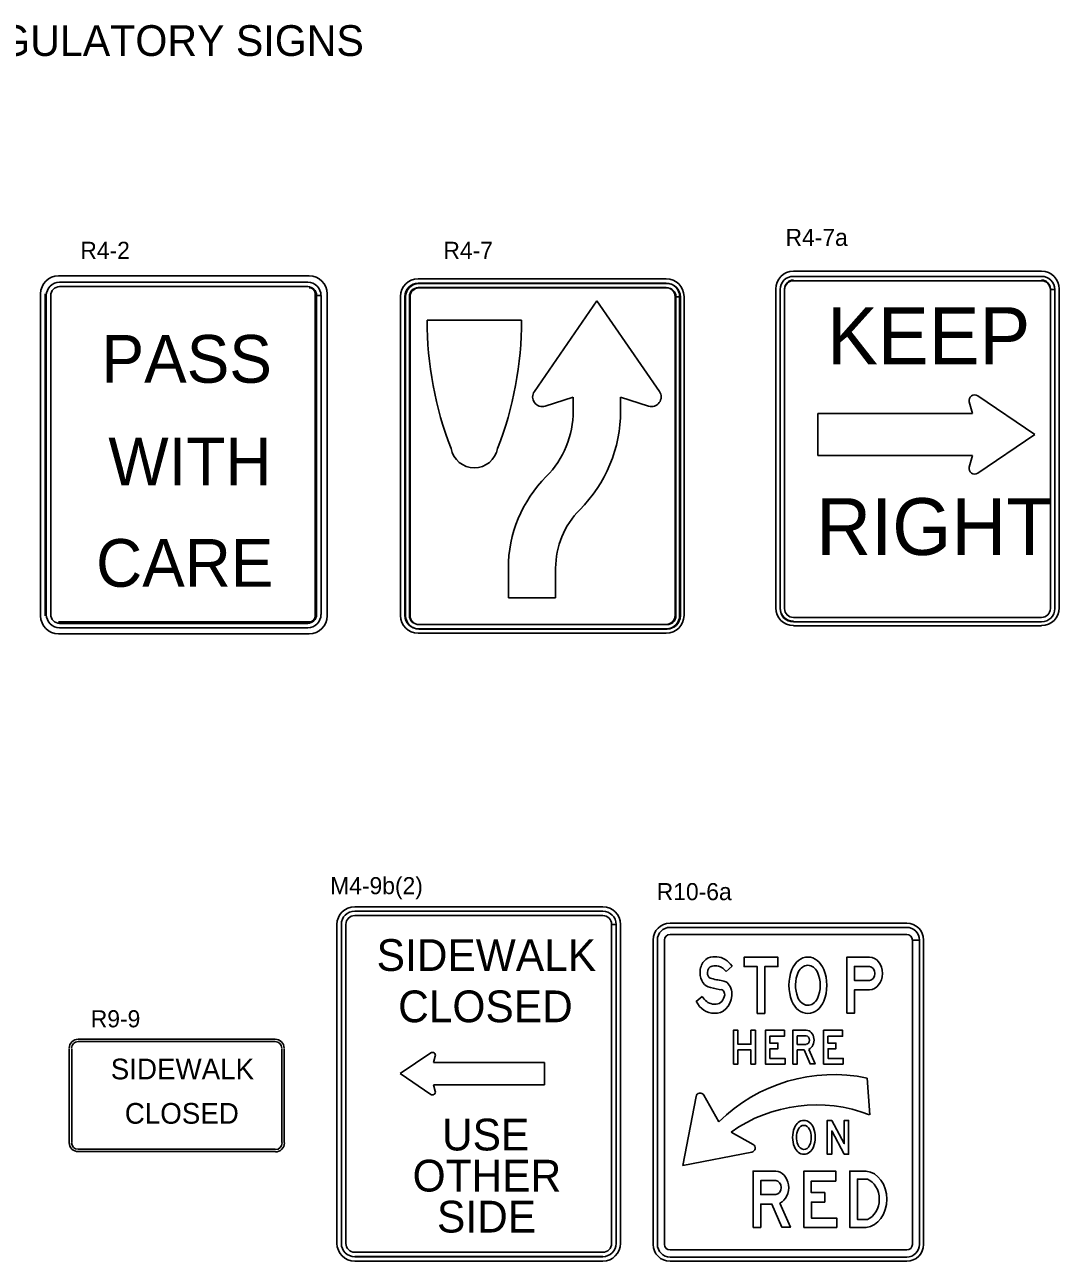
# Model space of a CAD drawing. Extents: x 1531.6 to 1538.58, y 1529.59 to 1539.33.
# Drawn here: x 1534.427 to 1538.059, y 1534.989 to 1539.332 of the extents above; entities that cross this region are included whole.
import ezdxf

# ---------------------------------------------------------------- set-up
doc = ezdxf.new("R2010")
doc.units = 0
for name, color, linetype in [('DETL-LINE', 7, 'Continuous'), ('DETL-NOTE', 7, 'Continuous'), ('DETL-TITL', 7, 'Continuous'), ('USER-BORD', 7, 'Continuous')]:
    doc.layers.add(name, color=color, linetype=linetype)

# ---------------------------------------------------------------- blocks, each defined once
blk = doc.blocks.new('EBK830')
at = {"layer": 'USER-BORD'}
for p, q in [((19.2, 20.1), (16.06, 17.76)), ((0, 5.1), (3.29, 7.2))]:
    blk.add_line(p, q, dxfattribs=at)
for centre, radius, start, end in [((8.82, 17.32), 6.73, 88.8922, 179.7586), ((10, 13.17), 10.93, 84.3792, 95.4986), ((10.65, 12.82), 11.23, 40.4161, 87.8422), ((8.44, 17.26), 6.35, 179.1866, 262.9776), ((8.82, 17.32), 2.83, 94.4353, 180.1618), ((8.44, 17.26), 2.45, 178.7407, 247.3216), ((10.01, 11.65), 8.61, 77.3888, 99.3796), ((10.65, 12.82), 7.33, 42.3579, 80.2675), ((18.43, 59.96), 46.27, 256.3309, 264.6653), ((18.43, 59.96), 50.17, 257.6081, 264.6653), ((11.77, 2.75), 11.39, 65.6571, 78.0474), ((12.65, 7.91), 6.47, 356.2163, 53.7856), ((9.6, 11.59), 7.68, 214.8089, 262.9285), ((10.37, 8.8), 8.83, 264.982, 351.4116), ((10.37, 8.8), 4.93, 273.4628, 349.3461), ((11.77, 2.75), 7.49, 69.1712, 78.0474), ((12.65, 7.91), 2.57, 359.563, 45.8128), ((9.6, 11.59), 11.58, 214.036, 269.995), ((10.06, 13.59), 9.73, 261.6866, 273.58), ((12.65, 7.91), 6.47, 317.7059, 321.0526)]:
    blk.add_arc(centre, radius, start, end, dxfattribs=at)
blk = doc.blocks.new('EBK840')
at = {"layer": 'USER-BORD'}
blk.add_lwpolyline([(11.0241, -0.0679), (7.028, -0.0679), (7.028, 19.9126), (0.026, 19.9126), (0.026, 23.9087), (18.026, 23.9087), (18.026, 19.9126), (11.0241, 19.9126)], close=True, dxfattribs=at)
blk = doc.blocks.new('EBK790')
at = {"layer": 'USER-BORD'}
for centre, radius, start, end in [((10, 14.51), 9.43, 26.0505, 153.9495), ((14.77, 11.93), 14.84, 153.1125, 206.8875), ((14.77, 11.93), 11.34, 150.334, 206.8875), ((10, 14.51), 5.93, 30.8734, 149.1266), ((5.23, 11.93), 11.34, 330.334, 29.666), ((5.23, 11.93), 14.84, 333.1125, 26.8875), ((10, 9.36), 5.93, 206.0505, 329.1266), ((10, 9.36), 9.43, 206.0505, 333.9495)]:
    blk.add_arc(centre, radius, start, end, dxfattribs=at)
blk = doc.blocks.new('EBK800')
at = {"layer": 'USER-BORD'}
for points in [[(0, 0), (0, 23.98), (4, 23.98), (12, 23.98)], [(12, 19.98), (4, 19.98), (4, 13.98), (12, 13.98)], [(12, 9.98), (4, 9.98), (4, 0), (0, 0)]]:
    blk.add_lwpolyline(points, dxfattribs=at)
for radius, start, end in [(7, 270.7924, 89.2076), (3, 271.865, 88.135)]:
    blk.add_arc((11.9, 16.98), radius, start, end, dxfattribs=at)
blk = doc.blocks.new('EBK720')
at = {"layer": 'USER-BORD'}
blk.add_lwpolyline([(0, 0), (0, 24), (4, 24), (4, 14), (15.5, 14), (15.5, 24), (19.5, 24), (19.5, 0), (15.5, 0), (15.5, 10), (4, 10), (4, 0)], close=True, dxfattribs=at)
blk = doc.blocks.new('EBK690')
at = {"layer": 'USER-BORD'}
blk.add_lwpolyline([(17.4295, 0), (17.4295, 4), (3.9496, 4), (3.9496, 10.8235), (11.0254, 10.8235), (11.0254, 14.8235), (3.8378, 14.8235), (3.8378, 19.7541), (16.9123, 19.7541), (16.9123, 24.0149), (0, 24.0149), (0, 0)], close=True, dxfattribs=at)
blk = doc.blocks.new('EBK820')
at = {"layer": 'USER-BORD'}
for points in [[(0, 0), (0, 23.98), (4, 23.98), (12, 23.98)], [(12, 19.98), (4, 19.98), (4, 13.98), (12, 13.98)], [(14.28, 10.4), (19.8, 0.05), (15.3, 0.05), (10, 9.98), (4, 9.98), (4, 0), (0, 0)]]:
    blk.add_lwpolyline(points, dxfattribs=at)
for radius, start, end in [(7, 289.8173, 89.2076), (3, 271.865, 88.135)]:
    blk.add_arc((11.9, 16.98), radius, start, end, dxfattribs=at)
blk = doc.blocks.new('EBK780')
at = {"layer": 'USER-BORD'}
blk.add_lwpolyline([(15, 0), (3.9, 16.5), (3.9, 0), (0, 0), (0, 24), (3.9, 24), (15, 7.5), (15, 24), (18.9, 24), (18.9, 0)], close=True, dxfattribs=at)
blk = doc.blocks.new('EBK680')
at = {"layer": 'USER-BORD'}
for p, q in [((8.75, 24), (8.75, 24)), ((9.36, 20.61), (9.36, 20.61))]:
    blk.add_line(p, q, dxfattribs=at)
for points in [[(8.75, 0), (0, 0), (0, 24), (8.75, 24)], [(9.36, 20.61), (4.05, 20.61), (4.05, 3.4), (9.36, 3.4)]]:
    blk.add_lwpolyline(points, dxfattribs=at)
for centre, radius, start, end in [((7.65, 12), 12.05, 275.2185, 84.7815), ((6.65, 12), 9.02, 287.4703, 72.5297)]:
    blk.add_arc(centre, radius, start, end, dxfattribs=at)

msp = doc.modelspace()

# ---------------------------------------------------------------- linework, layer by layer
at = {"layer": 'DETL-LINE'}
for p, q in [((1535.4256, 1538.4501), (1534.5453, 1538.4501)), ((1537.9972, 1538.4659), (1537.1259, 1538.4659)), ((1534.549, 1538.4275), (1535.4202, 1538.4275)), ((1535.4202, 1538.4119), (1534.549, 1538.4119)), ((1536.6795, 1538.4395), (1535.8083, 1538.4395)), ((1536.6795, 1538.424), (1535.8083, 1538.424)), ((1536.6795, 1538.4084), (1535.8083, 1538.4084)), ((1535.8108, 1538.4231), (1536.6821, 1538.4231)), ((1536.6821, 1538.4075), (1535.8108, 1538.4075)), ((1537.1258, 1538.4481), (1537.997, 1538.4481)), ((1537.997, 1538.4325), (1537.1258, 1538.4325)), ((1534.4824, 1538.3873), (1534.4824, 1537.2555)), ((1534.498, 1538.3873), (1534.498, 1537.2555)), ((1534.5024, 1537.2606), (1534.5024, 1538.3808)), ((1534.5179, 1538.3808), (1534.5179, 1537.2606)), ((1535.4465, 1537.2555), (1535.4465, 1538.3873)), ((1535.4514, 1537.2606), (1535.4514, 1538.3808)), ((1535.4514, 1538.3808), (1535.467, 1538.3808)), ((1535.467, 1538.3808), (1535.467, 1537.2606)), ((1535.4884, 1537.2555), (1535.4884, 1538.3873)), ((1535.7461, 1538.3773), (1535.7461, 1537.2571)), ((1535.7616, 1538.3773), (1535.7616, 1537.2571)), ((1535.7642, 1537.2562), (1535.7642, 1538.3764)), ((1535.7772, 1538.3773), (1535.7772, 1537.2571)), ((1535.7798, 1538.3764), (1535.7798, 1537.2562)), ((1536.4358, 1538.3617), (1536.2162, 1538.0438)), ((1536.4358, 1538.3617), (1536.6554, 1538.0438)), ((1536.6554, 1538.0438), (1536.4358, 1538.3617)), ((1536.6554, 1538.0438), (1536.4358, 1538.3617)), ((1536.7106, 1537.2571), (1536.7106, 1538.3773)), ((1536.7132, 1537.2562), (1536.7132, 1538.3764)), ((1536.7132, 1538.3764), (1536.7288, 1538.3764)), ((1536.7262, 1537.2571), (1536.7262, 1538.3773)), ((1536.7288, 1538.3764), (1536.7288, 1537.2562)), ((1536.7418, 1537.2571), (1536.7418, 1538.3773)), ((1537.0637, 1538.4038), (1537.0637, 1537.2836)), ((1537.0792, 1537.2812), (1537.0792, 1538.4014)), ((1537.0793, 1538.4038), (1537.0793, 1537.2836)), ((1537.0947, 1538.4014), (1537.0947, 1537.2812)), ((1537.0948, 1538.4038), (1537.0948, 1537.2836)), ((1538.0282, 1537.2812), (1538.0282, 1538.4014)), ((1538.0282, 1538.4014), (1538.0438, 1538.4014)), ((1538.0283, 1537.2836), (1538.0283, 1538.4038)), ((1538.0438, 1538.4014), (1538.0438, 1537.2812)), ((1538.0439, 1537.2836), (1538.0439, 1538.4038)), ((1538.0594, 1537.2836), (1538.0594, 1538.4038)), ((1535.8394, 1538.2943), (1536.1713, 1538.2943)), ((1536.1713, 1538.2943), (1536.1713, 1538.2943)), ((1536.2542, 1537.9925), (1536.3529, 1538.0241)), ((1536.3529, 1538.0241), (1536.3529, 1537.9753)), ((1536.5188, 1537.9753), (1536.5188, 1538.0241)), ((1536.5188, 1538.0241), (1536.6174, 1537.9925)), ((1536.6554, 1538.0438), (1536.6554, 1538.0438)), ((1537.7728, 1538.0285), (1537.7729, 1538.0285)), ((1537.7729, 1538.0285), (1537.9734, 1537.8926)), ((1537.7549, 1537.9667), (1537.7434, 1538.0071)), ((1537.2119, 1537.8187), (1537.2119, 1537.9667)), ((1537.2119, 1537.9667), (1537.7549, 1537.9667)), ((1537.9734, 1537.8926), (1537.7729, 1537.7569)), ((1537.7549, 1537.8187), (1537.2119, 1537.8187)), ((1537.7434, 1537.7782), (1537.7549, 1537.8187)), ((1536.1248, 1537.4231), (1536.1248, 1537.3194)), ((1536.2907, 1537.3194), (1536.2907, 1537.4231)), ((1536.1248, 1537.3194), (1536.2907, 1537.3194)), ((1534.5453, 1537.2345), (1535.4256, 1537.2345)), ((1537.1258, 1537.2501), (1537.997, 1537.2501)), ((1537.997, 1537.2346), (1537.1258, 1537.2346)), ((1534.5453, 1537.1926), (1535.4256, 1537.1926)), ((1534.549, 1537.2295), (1535.4202, 1537.2295)), ((1535.4202, 1537.214), (1534.549, 1537.214)), ((1535.8083, 1537.2259), (1536.6795, 1537.2259)), ((1535.8083, 1537.2104), (1536.6795, 1537.2104)), ((1535.8083, 1537.1949), (1536.6795, 1537.1949)), ((1535.8108, 1537.2251), (1536.6821, 1537.2251)), ((1536.6821, 1537.2096), (1535.8108, 1537.2096)), ((1537.1259, 1537.2213), (1537.9972, 1537.2213)), ((1535.5852, 1536.2343), (1536.4565, 1536.2343)), ((1535.5852, 1536.2188), (1536.4565, 1536.2188)), ((1535.5852, 1536.2187), (1536.4565, 1536.2187)), ((1535.5852, 1536.2032), (1536.4565, 1536.2032)), ((1536.4565, 1536.2032), (1535.5852, 1536.2032)), ((1535.523, 1535.0519), (1535.523, 1536.1721)), ((1535.5386, 1535.0519), (1535.5386, 1536.1721)), ((1535.5386, 1535.0519), (1535.5386, 1536.1721)), ((1535.554, 1535.0519), (1535.554, 1536.1721)), ((1535.5541, 1536.1721), (1535.5541, 1535.0519)), ((1536.4876, 1536.1721), (1536.4876, 1535.0519)), ((1536.4876, 1535.0519), (1536.4876, 1536.1721)), ((1536.4876, 1536.1721), (1536.5032, 1536.1721)), ((1536.5032, 1536.1721), (1536.5032, 1535.0519)), ((1536.5032, 1536.1721), (1536.5032, 1535.0519)), ((1536.5187, 1536.1721), (1536.5187, 1535.0519)), ((1537.5238, 1536.1765), (1536.6926, 1536.1765)), ((1537.5238, 1536.1617), (1536.6926, 1536.1617)), ((1536.6332, 1536.1172), (1536.6332, 1535.0485)), ((1536.6481, 1536.1172), (1536.6481, 1535.0485)), ((1536.6728, 1535.0485), (1536.6728, 1536.1172)), ((1536.6926, 1536.1369), (1537.5238, 1536.1369)), ((1537.5683, 1536.1172), (1537.5436, 1536.1172)), ((1537.5436, 1536.1172), (1537.5436, 1535.0485)), ((1537.5683, 1535.0485), (1537.5683, 1536.1172)), ((1537.5832, 1535.0485), (1537.5832, 1536.1172)), ((1535.306, 1535.769), (1534.6144, 1535.769)), ((1535.306, 1535.7606), (1534.6144, 1535.7606)), ((1534.583, 1535.7351), (1534.583, 1535.4066)), ((1534.5914, 1535.7351), (1534.5914, 1535.4066)), ((1535.3291, 1535.4066), (1535.3291, 1535.7351)), ((1535.3374, 1535.4066), (1535.3374, 1535.7351)), ((1535.8526, 1535.7209), (1535.745, 1535.6481)), ((1535.8622, 1535.6877), (1535.8684, 1535.7096)), ((1536.252, 1535.6877), (1535.8622, 1535.6877)), ((1536.252, 1535.6084), (1536.252, 1535.6877)), ((1535.745, 1535.6481), (1535.8526, 1535.5752)), ((1537.3937, 1535.5037), (1537.3848, 1535.6323)), ((1537.3848, 1535.6323), (1537.3848, 1535.6323)), ((1535.8684, 1535.5867), (1535.8622, 1535.6084)), ((1535.8622, 1535.6084), (1536.252, 1535.6084)), ((1536.7838, 1535.568), (1536.7371, 1535.3256)), ((1536.864, 1535.4789), (1536.8113, 1535.5725)), ((1536.9841, 1535.3997), (1536.9073, 1535.4429)), ((1534.6144, 1535.3825), (1535.306, 1535.3825)), ((1534.6144, 1535.3741), (1535.306, 1535.3741)), ((1536.7371, 1535.3256), (1536.9796, 1535.3722)), ((1535.5852, 1535.0208), (1536.4565, 1535.0208)), ((1536.4565, 1535.0207), (1535.5852, 1535.0207)), ((1537.5238, 1535.0287), (1536.6926, 1535.0287)), ((1537.5683, 1535.0485), (1537.5683, 1535.0485)), ((1536.4565, 1535.0053), (1535.5852, 1535.0053)), ((1536.4565, 1535.0052), (1535.5852, 1535.0052)), ((1536.4565, 1534.9897), (1535.5852, 1534.9897)), ((1536.6926, 1535.0039), (1537.5238, 1535.0039)), ((1536.6926, 1534.9891), (1537.5238, 1534.9891))]:
    msp.add_line(p, q, dxfattribs=at)
for centre, radius, start, end in [((1534.5452, 1538.3872), 0.0629, 90, 180), ((1535.4255, 1538.3872), 0.0629, 0, 90), ((1537.1259, 1538.4038), 0.0622, 90, 180), ((1537.9972, 1538.4038), 0.0622, 0, 90), ((1534.549, 1538.3808), 0.0467, 90, 180), ((1534.549, 1538.3808), 0.0311, 90, 180), ((1535.4202, 1538.3808), 0.0467, 0, 90), ((1535.4202, 1538.3808), 0.0311, 0, 90), ((1535.4255, 1538.3872), 0.021, 0, 90), ((1535.8083, 1538.3773), 0.0622, 90, 180), ((1535.8083, 1538.3773), 0.0467, 90, 180), ((1535.8109, 1538.3764), 0.0467, 90, 180), ((1535.8083, 1538.3773), 0.0311, 90, 180), ((1535.8109, 1538.3764), 0.0311, 90, 180), ((1536.6795, 1538.3773), 0.0622, 0, 90), ((1536.6795, 1538.3773), 0.0467, 0, 90), ((1536.6795, 1538.3773), 0.0311, 0, 90), ((1536.6821, 1538.3764), 0.0467, 0, 90), ((1536.6821, 1538.3764), 0.0311, 0, 90), ((1537.1258, 1538.4014), 0.0467, 90, 180), ((1537.1258, 1538.4014), 0.0311, 90, 180), ((1537.1259, 1538.4038), 0.0311, 90, 180), ((1537.997, 1538.4014), 0.0467, 0, 90), ((1537.997, 1538.4014), 0.0311, 0, 90), ((1537.9972, 1538.4038), 0.0311, 0, 90), ((1537.084, 1538.2939), 1.2447, 179.9823, 201.2203), ((1534.9266, 1538.2939), 1.2447, 338.7797, 0.0177), ((1536.2439, 1538.0246), 0.0337, 145.3645, 287.7219), ((1536.6277, 1538.0246), 0.0337, 252.2781, 34.6356), ((1537.762, 1538.0124), 0.0194, 55.8869, 195.9549), ((1536.0263, 1537.9754), 0.3266, 315.1342, 0), ((1536.0263, 1537.9754), 0.4925, 315.1342, 0), ((1536.0053, 1537.8587), 0.083, 190.6013, 349.3987), ((1537.762, 1537.7729), 0.0194, 164.0451, 304.1131), ((1536.5812, 1537.423), 0.4564, 135.1342, 180), ((1536.5812, 1537.423), 0.2904, 135.1342, 180), ((1537.1259, 1537.2836), 0.0622, 180, 270), ((1537.1259, 1537.2836), 0.0467, 180, 270), ((1537.1258, 1537.2812), 0.0467, 180, 270), ((1537.1258, 1537.2812), 0.0311, 180, 270), ((1537.997, 1537.2812), 0.0467, 270, 0), ((1537.997, 1537.2812), 0.0311, 270, 0), ((1537.9972, 1537.2836), 0.0622, 270, 0), ((1534.5452, 1537.2554), 0.0629, 180, 270), ((1534.549, 1537.2606), 0.0467, 180, 270), ((1534.549, 1537.2606), 0.0311, 180, 270), ((1535.4202, 1537.2606), 0.0467, 270, 0), ((1535.4202, 1537.2606), 0.0311, 270, 0), ((1535.4255, 1537.2554), 0.021, 270, 0), ((1535.4255, 1537.2554), 0.0629, 270, 0), ((1535.8083, 1537.2571), 0.0622, 180, 270), ((1535.8083, 1537.2571), 0.0467, 180, 270), ((1535.8109, 1537.2562), 0.0467, 180, 270), ((1535.8083, 1537.2571), 0.0311, 180, 270), ((1535.8109, 1537.2562), 0.0311, 180, 270), ((1536.6795, 1537.2571), 0.0622, 270, 0), ((1536.6795, 1537.2571), 0.0467, 270, 0), ((1536.6795, 1537.2571), 0.0311, 270, 0), ((1536.6821, 1537.2562), 0.0467, 270, 0), ((1536.6821, 1537.2562), 0.0311, 270, 0), ((1535.5852, 1536.1721), 0.0622, 90, 180), ((1536.4565, 1536.1721), 0.0622, 0, 90), ((1535.5852, 1536.1721), 0.0467, 90, 180), ((1535.5852, 1536.1721), 0.0467, 90, 180), ((1535.5852, 1536.1721), 0.0311, 90, 180), ((1535.5852, 1536.1721), 0.0311, 90, 180), ((1536.4564, 1536.1721), 0.0467, 0, 90), ((1536.4564, 1536.1721), 0.0311, 0, 90), ((1536.4565, 1536.1721), 0.0467, 0, 90), ((1536.4565, 1536.1721), 0.0311, 0, 90), ((1536.6925, 1536.1172), 0.0594, 90, 180), ((1536.6925, 1536.1172), 0.0445, 90, 180), ((1537.5238, 1536.1172), 0.0594, 0, 90), ((1537.5238, 1536.1172), 0.0445, 0, 90), ((1536.6925, 1536.1172), 0.0198, 90, 180), ((1537.5238, 1536.1172), 0.0198, 0, 90), ((1534.6143, 1535.7376), 0.0314, 90, 180), ((1534.6143, 1535.7376), 0.0231, 90, 180), ((1535.306, 1535.7376), 0.0314, 0, 90), ((1535.306, 1535.7376), 0.0231, 0, 90), ((1535.8584, 1535.7124), 0.0104, 344.0451, 124.1131), ((1537.2665, 1535.0732), 0.5715, 78.0573, 134.774), ((1535.8584, 1535.5838), 0.0104, 235.8869, 15.9549), ((1536.7983, 1535.5652), 0.0148, 29.4108, 169.1093), ((1537.2071, 1535.0188), 0.5195, 68.9605, 125.2585), ((1534.6143, 1535.4055), 0.0314, 180, 270), ((1534.6143, 1535.4055), 0.0231, 180, 270), ((1535.3072, 1535.4045), 0.0231, 270, 0), ((1535.3072, 1535.4045), 0.0314, 270, 0), ((1536.9767, 1535.3868), 0.0148, 280.8908, 60.5893), ((1535.5852, 1535.0519), 0.0622, 180, 270), ((1535.5852, 1535.0519), 0.0467, 180, 270), ((1535.5852, 1535.0519), 0.0467, 180, 270), ((1535.5852, 1535.0519), 0.0311, 180, 270), ((1535.5852, 1535.0519), 0.0311, 180, 270), ((1536.4564, 1535.0519), 0.0467, 270, 0), ((1536.4564, 1535.0519), 0.0311, 270, 0), ((1536.4565, 1535.0519), 0.0311, 270, 0), ((1536.4565, 1535.0519), 0.0467, 270, 0), ((1536.4565, 1535.0519), 0.0622, 270, 0), ((1536.6925, 1535.0485), 0.0594, 180, 270), ((1536.6925, 1535.0485), 0.0445, 180, 270), ((1536.6925, 1535.0485), 0.0198, 180, 270), ((1537.5238, 1535.0485), 0.0594, 270, 0), ((1537.5238, 1535.0485), 0.0198, 270, 0), ((1537.5238, 1535.0485), 0.0445, 270, 0)]:
    msp.add_arc(centre, radius, start, end, dxfattribs=at)

# ---------------------------------------------------------------- block references
for name, p, xscale, yscale in [('EBK830', (1536.7841, 1535.8599), 0.006597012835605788, 0.008246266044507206), ('EBK840', (1536.9524, 1535.8599), 0.006597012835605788, 0.008246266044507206), ('EBK790', (1537.1106, 1535.8599), 0.006597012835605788, 0.008246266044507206), ('EBK800', (1537.3136, 1535.8599), 0.006597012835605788, 0.008246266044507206), ('EBK720', (1536.9152, 1535.6818), 0.003958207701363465, 0.004947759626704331), ('EBK690', (1537.0275, 1535.6818), 0.003958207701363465, 0.004947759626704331), ('EBK820', (1537.1236, 1535.6818), 0.003958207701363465, 0.004947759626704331), ('EBK690', (1537.2317, 1535.6818), 0.003958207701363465, 0.004947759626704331), ('EBK790', (1537.1231, 1535.3652), 0.003958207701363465, 0.004947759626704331), ('EBK780', (1537.2448, 1535.3652), 0.003958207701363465, 0.004947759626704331), ('EBK820', (1536.9845, 1535.1079), 0.006597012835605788, 0.008246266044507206), ('EBK690', (1537.1629, 1535.1079), 0.006597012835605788, 0.008246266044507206), ('EBK680', (1537.3239, 1535.1079), 0.006597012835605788, 0.008246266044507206)]:
    msp.add_blockref(name, p, dxfattribs=dict(at, xscale=xscale, yscale=yscale))

# ---------------------------------------------------------------- texts
for s, height, p in [('KEEP', 0.20003, (1537.2439, 1538.1396)), ('PASS', 0.16767, (1534.6963, 1538.0745)), ('WITH', 0.16767, (1534.7202, 1537.7138)), ('RIGHT', 0.19953, (1537.206, 1537.4695)), ('CARE', 0.16767, (1534.6772, 1537.3578)), ('SIDEWALK', 0.1115, (1535.6623, 1536.0088)), ('CLOSED', 0.1115, (1535.7378, 1535.8286)), ('SIDEWALK', 0.07285, (1534.7286, 1535.6279)), ('CLOSED', 0.07285, (1534.7779, 1535.4721)), ('USE', 0.1115, (1535.8918, 1535.3783)), ('OTHER', 0.1115, (1535.7886, 1535.2341)), ('SIDE', 0.1115, (1535.8742, 1535.0901))]:
    msp.add_text(s, height=height, dxfattribs=at).set_placement(p)
at = {"layer": 'DETL-NOTE'}
for s, p in [('R4-7a', (1537.0981, 1538.555)), ('R4-2', (1534.6218, 1538.5095)), ('R4-7', (1535.8968, 1538.5095)), ('M4-9b(2)', (1535.4992, 1536.2783)), ('R10-6a', (1536.6459, 1536.2573)), ('R9-9', (1534.6585, 1535.8107))]:
    msp.add_text(s, height=0.06, dxfattribs=at).set_placement(p)
at = {"layer": 'DETL-TITL'}
msp.add_text('REGULATORY SIGNS', height=0.108, dxfattribs=at).set_placement((1534.1329, 1539.2222))

doc.saveas('drawing.dxf')
